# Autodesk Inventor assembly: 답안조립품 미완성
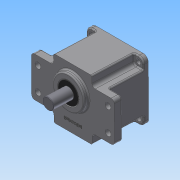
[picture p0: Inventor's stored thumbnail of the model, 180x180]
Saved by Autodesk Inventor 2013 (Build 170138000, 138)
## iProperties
Created: 2014-12
Part Number: 답안조립품 미완성
Document SubType Name: Assembly
Designer: Administrator
Author: Administrator
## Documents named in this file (12)
- C:\Users\Administrator\Desktop\Inventor2급-임성민\답안조립품 미완성.iam
- C:\Users\Administrator\Desktop\Inventor2급-임성민\본체.ipt
- C:\Users\Administrator\Desktop\Inventor2급-임성민\M4x0.5x16.ipt
- C:\Users\Administrator\Desktop\Inventor2급-임성민\메인축.ipt
- C:\Users\Administrator\Desktop\Inventor2급-임성민\베어링 608.ipt
- 베어링 608.ipt
- C:\Users\Administrator\Desktop\Inventor2급-임성민\베어링 6003.ipt
- 베어링 6003.ipt
- C:\Users\Administrator\Desktop\Inventor2급-임성민\서브축.ipt
- C:\Users\Administrator\Desktop\Inventor2급-임성민\오일실 8x22x7.ipt
- C:\Users\Administrator\Desktop\Inventor2급-임성민\오일실 17x32x8.ipt
- C:\Users\Administrator\Desktop\Inventor2급-임성민\커버.ipt
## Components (4 placed, 1 different names)
1. M4x0.5x12:1 — Insert:1
2. M4x0.5x12:2
3. M4x0.5x12:3
4. M4x0.5x12:4
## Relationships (1: Insert 1)
- Insert:1: M4x0.5x12:1
